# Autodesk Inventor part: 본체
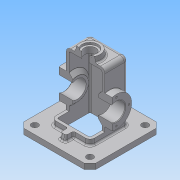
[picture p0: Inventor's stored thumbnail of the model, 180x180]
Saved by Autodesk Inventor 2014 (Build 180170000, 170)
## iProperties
Created: 2016-02
Part Number: 본체
Material: Generic
Document SubType Name: Modeling
Designer: User
Density: 1 g/cm^3
Appearance: Default
Author: User
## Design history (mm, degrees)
sketch "스케치1"
  geometry: L1 (-35, 35)-(35, 35); L2 (35, 35)-(35, -35); L3 (35, -35)-(-35, -35); L4 (-35, -35)-(-35, 35); L5 (-35, 35)-(35, -35); 2 further points
  constraints: 10 end point, 2 parallel, 1 coincident, 1 horizontal, 1 midpoint, 1 perpendicular
  dimensions: "d0" = 70 distance of L1.start L1.end; "d1" = 70 distance of L3.end L1.start
extrude "돌출1" new body sketch "스케치1" distance "d2" = 120; taper "d3" = 0 deg
feature "쉘1" dims "d4" = 5
sketch "스케치2"
  geometry: L1 (35, 35)-(-35, 35) reference; L2 (-35, 35)-(-35, -35) reference; L3 (-35, -35)-(35, -35) reference; L4 (35, -35)-(35, 35) reference; L5 (-65, 65)-(65, 65); L6 (65, 65)-(65, -65); L7 (65, -65)-(-65, -65); L8 (-65, -65)-(-65, 65); L9 (-65, 65)-(65, -65); 2 further points
  constraints: 10 end point, 2 parallel, 1 coincident, 1 horizontal, 1 midpoint, 1 perpendicular
  dimensions: "d5" = 130 distance of L5.start L5.end; "d6" = 130 distance of L7.end L5.start
extrude "돌출2" join sketch "스케치2" distance "d7" = 10; taper "d8" = 0 deg
sketch "스케치4"
  geometry: L1 (-30, 0)-(30, 0) reference; L2 (23, 55)-(30, 55); L3 (30, 0)-(30, 115) reference; L4 (30, 82.5)-(23, 75.5); L5 (23, 55)-(23, 75.5); L6 (30, 82.5)-(30, 55); 1 further point
  constraints: 8 end point, 3 parallel, 1 point on line
  dimensions: "d9" = 55 distance between parallel lines of L1 L2; "d12" = 135 deg angle of L4 L3; "d14" = 27.5 vertical distance of L2.start L4.start; "d15" = 7 distance between parallel lines of L5 L3
revolve "회전1" sketch "스케치4" stored, may be unused: angle "d16" = 90 deg
sketch "스케치5"
  geometry: L1 (10, -30)-(10, 100) reference; C1 r 27.5 at (-45, 35); 2 further points
  constraints: 1 centre point, 1 horizontal alignment, 1 midpoint
  dimensions: "d18" = 55 diameter of C1; "d19" = 55 distance of point (10, 35) C1.centre
extrude "돌출3" join sketch "스케치5" distance "d20" = 13; taper "d21" = 0 deg
sketch "스케치7"
  geometry: L1 (-35, 120)-(35, 120) reference; L2 (-18.237, 130)-(0, 130); L3 (0, 120)-(0, 130); L4 (-18.237, 130)-(-20, 120); L5 (-20, 120)-(-20, 130); 3 further points
  constraints: 8 end point, 2 parallel, 1 midpoint, 1 point on line, 1 vertical
  dimensions: "d23" = 10 distance between parallel lines of L1 L2; "d25" = 10 deg angle of L5 L4; "d26" = 20 distance from line of L4.end L3
revolve "회전2" sketch "스케치7" stored, may be unused: angle "d27" = 90 deg
hole "구멍1" diameter "d30" = 32; stored, may be unused: countersink angle "d34" = 90 deg, drill point angle "d36" = 0 deg; dims "d28" = 10, "d29" = 10, "d31" = 6, "d32" = 4, "d33" = 2, "d35" = 48
hole "구멍2" diameter "d39" = 21; stored, may be unused: countersink angle "d43" = 90 deg, drill point angle "d45" = 0 deg; dims "d37" = 10, "d38" = 10, "d40" = 6, "d41" = 28, "d42" = 4, "d44" = 48
sketch "스케치8"
  geometry: C1 r 16 at (0, 0) reference; 2 further points
  constraints: 1 vertical alignment
  dimensions: "d46" = 22.5 distance of point (0, 22.5) C1.centre
hole "구멍3" sketch "스케치8" at (0, 22.5) diameter "d47" = 3.242; stored, may be unused: countersink angle "d51" = 90 deg, drill point angle "d53" = 0 deg; dims "d48" = 8, "d49" = 28, "d50" = 4, "d52" = 10
sketch "스케치9"
  geometry: L1 (-30, 115)-(-30, 0) reference; L2 (-30, 0)-(-65, 0) reference; L3 (-65, 0)-(-65, 10) reference; L4 (-65, 10)-(-35, 10) reference; L5 (-35, 10)-(-35, 120) reference; L6 (-35, 120)-(-20, 120) reference; L7 (-20, 120)-(-18.237, 130) reference; L8 (-18.237, 130)-(-14, 130) reference; L9 (-14, 130)-(-14, 126) reference; L10 (-14, 126)-(-10.5, 126) reference; L11 (-10.5, 126)-(-10.5, 115) reference; L12 (-10.5, 115)-(-30, 115) reference; L13 (30, 0)-(30, 115) reference; L14 (30, 115)-(10.5, 115) reference; L15 (10.5, 115)-(10.5, 126) reference; L16 (10.5, 126)-(14, 126) reference; L17 (14, 126)-(14, 130) reference; L18 (14, 130)-(18.237, 130) reference; L19 (18.237, 130)-(20, 120) reference; L20 (20, 120)-(35, 120) reference; L21 (35, 120)-(35, 10) reference; L22 (35, 10)-(65, 10) reference; L23 (65, 10)-(65, 0) reference; L24 (65, 0)-(30, 0) reference; L25 (-35, 95.069)-(-50, 10); 1 further point
  constraints: 2 end point, 1 midpoint, 1 point on line
  dimensions: "d58" = 15 distance from line of L25.end L3; "d59" = 10 deg angle of L25 L3
feature "리브1" sketch "스케치9" dims "d60" = 1, "d61" = 10, "d62" = 0, "d63" = 0, "d64" = 1, "d65" = 1
fillet "모깎기2" dims "d66" = 8
chamfer "모따기1" distance "d67" = 10; stored, may be unused: second distance "d68" = 2, angle "d69" = 45 deg
sketch "스케치10"
  geometry: L1 (-65, 55)-(-65, -55) reference; L2 (55, 65)-(-55, 65) reference; L3 (-5, 50)-(5, 50) reference; L4 (0, 65)-(0, 50); L5 (-65, 0)-(-50, 0); 2 further points
  constraints: 4 end point, 3 midpoint, 1 perpendicular
  dimensions: "d70" = 50 distance from line of point (-50, 50) L4; "d71" = 50 distance from line of L5 point (-50, 50)
hole "구멍4" sketch "스케치10" at (-50, 50) diameter "d72" = 12; stored, may be unused: countersink angle "d76" = 90 deg, drill point angle "d78" = 0 deg; dims "d73" = 8, "d74" = 28, "d75" = 4, "d77" = 10
fillet "모깎기3" dims "d85" = 0.5
fillet "모깎기4" dims "d86" = 0.5
fillet "모깎기5" dims "d87" = 3
fillet "모깎기6" dims "d88" = 3
fillet "모깎기7" dims "d89" = 3
fillet "모깎기8" dims "d90" = 8
fillet "모깎기9" dims "d91" = 3
fillet "모깎기10" dims "d92" = 3
chamfer "모따기2" distance "d93" = 1; stored, may be unused: second distance "d94" = 2, angle "d95" = 45 deg
sketch "스케치15"
  geometry: L1 (-57, 27)-(-7.416, 27) reference; L2 (-57, -27)-(-57, 27) reference; L3 (-7.416, -27)-(-57, -27) reference; L4 (-75, 18.237)-(-75, -18.237) reference; L5 (-42.5, 18.237)-(-42.5, -18.237); A1 r 28 centre (0, 0) between (-7.416, 27) and (-7.416, -27) reference; 1 further point
  constraints: 2 end point, 1 parallel, 1 vertical
  dimensions: "d101" = 32.5 distance between parallel lines of L5 L4
sketch "스케치17"
  geometry: L1 (-60.847, 153.985)-(-8.006, 153.985); L2 (-8.006, 153.985)-(-8.006, 20.549); L3 (-8.006, 20.549)-(-60.847, 20.549); L4 (-60.847, 20.549)-(-60.847, 153.985); 1 further point
  constraints: 8 end point, 2 parallel, 1 horizontal, 1 perpendicular
extrude "돌출5" cut sketch "스케치17" stored distance "d104" = 100; taper "d105" = 0 deg
node "솔리드1"
mirror "대칭1"
mirror "대칭2"
mirror "대칭3"
pattern_circular "원형 패턴1" dims angle "d55" = 360 deg
mirror "대칭4"
mirror "대칭5"
pattern_linear "직사각형 패턴1" dims "d81" = 100
node "절단 모서리 투영1"
other parameters: "d11" = 7
